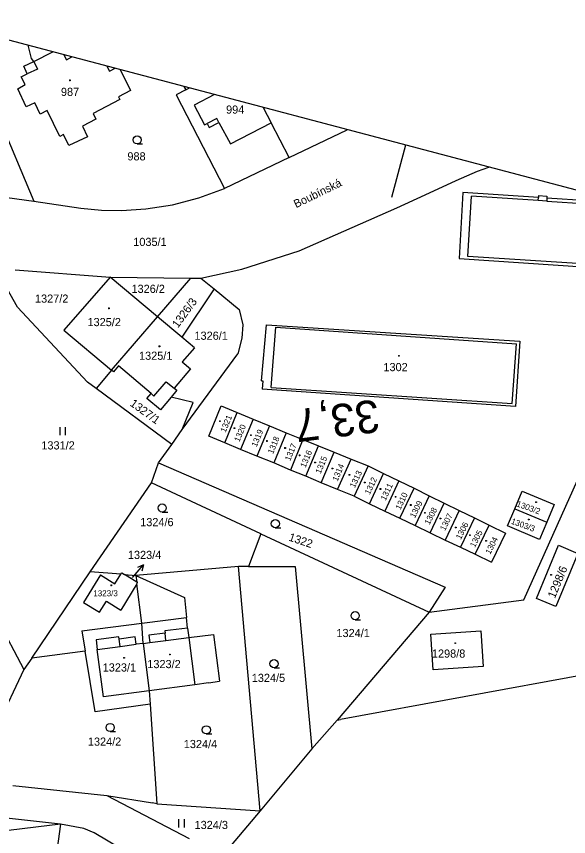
# Model space of a CAD drawing. Extents: x -805011 to -803920, y -1150790 to -1150234.
# Drawn here: x -804600.8 to -804499.4, y -1150469 to -1150318.2 of the extents above; entities that cross this region are included whole.
import ezdxf

# ---------------------------------------------------------------- set-up
doc = ezdxf.new("R2010")
doc.units = 0
for name, color, linetype in [('Default', 7, 'Continuous'), ('formát', 7, 'Continuous'), ('kilometráž - vrstava 7', 7, 'Continuous'), ('kn_celek - Cisla parcel pomocna', 7, 'Continuous'), ('kn_celek - Cisla pozemkovych parcel', 7, 'Continuous'), ('kn_celek - Cisla stavebnich parcel', 7, 'Continuous'), ('kn_celek - Dalsi prvky mapy popis', 7, 'Continuous'), ('kn_celek - Hranice parcel', 7, 'Continuous'), ('kn_celek - Vnitrni kresby', 7, 'Continuous'), ('kn_celek - Znacky budov', 7, 'Continuous'), ('kn_celek - Znacky kultur', 7, 'Continuous')]:
    doc.layers.add(name, color=color, linetype=linetype)

# ---------------------------------------------------------------- blocks, each defined once
blk = doc.blocks.new('304')
at = {"layer": 'Default'}
blk.add_line((-0.1, 0), (9.9, 0), dxfattribs=at)
blk.add_circle((-0.1, 7.5), 7.5, dxfattribs=at)
blk = doc.blocks.new('306')
at = {"layer": 'Default'}
for p, q in [((-5.2, 0), (-5.2, 15)), ((4.8, 0), (4.8, 15))]:
    blk.add_line(p, q, dxfattribs=at)
blk = doc.blocks.new('402')
at = {"layer": 'Default'}
for p, q in [((-0.8, 0.8), (0.7, 0.8)), ((-0.8, 0.8), (-0.8, -0.7)), ((0.7, 0.8), (0.7, -0.7)), ((0.7, -0.7), (-0.8, -0.7))]:
    blk.add_line(p, q, dxfattribs=at)
blk = doc.blocks.new('Z61')
at = {"layer": 'Default'}
for p, q in [((0, 0), (30, 0)), ((30, 0), (19.2, 5.3)), ((30, 0), (19.2, -5.3))]:
    blk.add_line(p, q, dxfattribs=at)

msp = doc.modelspace()

# ---------------------------------------------------------------- linework, layer by layer
at = {"layer": 'formát'}
for p, q in [((-804326.3, -1150395.58), (-804935.34, -1150234.42)), ((-804529.32, -1150341.86), (-804531.87, -1150351.53)), ((-804529.32, -1150341.86), (-804531.87, -1150351.53))]:
    msp.add_line(p, q, dxfattribs=at)
at = {"layer": 'kn_celek - Cisla parcel pomocna'}
msp.add_line((-804579.45, -1150421.34), (-804579.43, -1150421.32), dxfattribs=at)
at = {"layer": 'kn_celek - Hranice parcel'}
for p, q in [((-804610.94, -1150320.55), (-804597.6, -1150352.18)), ((-804598.01, -1150325.92), (-804598.68, -1150323.51)), ((-804597.63, -1150326.47), (-804594.11, -1150324.72)), ((-804599.42, -1150327.37), (-804597.63, -1150326.47)), ((-804597.63, -1150326.47), (-804598.01, -1150325.92)), ((-804592.08, -1150325.25), (-804591.63, -1150326.16)), ((-804591.63, -1150326.16), (-804590.6, -1150325.65)), ((-804598.84, -1150328.79), (-804599.42, -1150327.37)), ((-804584.18, -1150327.34), (-804583.71, -1150328.27)), ((-804583.71, -1150328.27), (-804582.68, -1150327.74)), ((-804581.77, -1150327.98), (-804579.86, -1150331.85)), ((-804599.96, -1150329.31), (-804598.84, -1150328.79)), ((-804599.21, -1150330.74), (-804599.96, -1150329.31)), ((-804600.53, -1150331.52), (-804599.21, -1150330.74)), ((-804599.01, -1150334.84), (-804600.53, -1150331.52)), ((-804579.86, -1150331.85), (-804582.06, -1150333)), ((-804569.69, -1150331.71), (-804571.48, -1150332.63)), ((-804570.05, -1150331.08), (-804569.69, -1150331.71)), ((-804569.69, -1150331.71), (-804569, -1150331.36)), ((-804581.8, -1150333.49), (-804586.74, -1150336.04)), ((-804582.06, -1150333), (-804581.8, -1150333.49)), ((-804571.48, -1150332.63), (-804562.59, -1150349.86)), ((-804597.45, -1150334.11), (-804599.01, -1150334.84)), ((-804596.43, -1150336.15), (-804597.45, -1150334.11)), ((-804595.18, -1150335.53), (-804596.43, -1150336.15)), ((-804592.86, -1150340.29), (-804595.18, -1150335.53)), ((-804555.45, -1150334.95), (-804553.98, -1150337.75)), ((-804586.74, -1150336.04), (-804586.19, -1150337.1)), ((-804586.19, -1150337.1), (-804588.68, -1150338.39)), ((-804588.68, -1150338.39), (-804587.78, -1150340.36)), ((-804550.72, -1150344.17), (-804553.98, -1150337.75)), ((-804592.13, -1150339.94), (-804592.86, -1150340.29)), ((-804591.19, -1150341.91), (-804592.13, -1150339.94)), ((-804550.72, -1150344.17), (-804540.02, -1150339.03)), ((-804587.78, -1150340.36), (-804591.19, -1150341.91)), ((-804550.72, -1150344.17), (-804562.59, -1150349.86)), ((-804516.1, -1150346.63), (-804513.99, -1150345.92)), ((-804520.04, -1150348.36), (-804516.1, -1150346.63)), ((-804525.7, -1150351.03), (-804520.04, -1150348.36)), ((-804567.3, -1150351.55), (-804562.59, -1150349.86)), ((-804518.79, -1150350.6), (-804519.49, -1150362.73)), ((-804504.91, -1150351.52), (-804518.79, -1150350.6)), ((-804608.15, -1150350.71), (-804597.6, -1150352.18)), ((-804572.16, -1150352.85), (-804567.3, -1150351.55)), ((-804530.92, -1150353.37), (-804525.7, -1150351.03)), ((-804504.89, -1150351.14), (-804504.91, -1150351.52)), ((-804504.89, -1150351.14), (-804503.35, -1150351.28)), ((-804503.35, -1150351.28), (-804503.36, -1150351.63)), ((-804488.71, -1150352.61), (-804503.36, -1150351.63)), ((-804597.6, -1150352.18), (-804588.95, -1150353.47)), ((-804588.95, -1150353.47), (-804585.18, -1150353.82)), ((-804581.48, -1150353.88), (-804577.03, -1150353.56)), ((-804577.03, -1150353.56), (-804572.16, -1150352.85)), ((-804548.89, -1150361.28), (-804530.92, -1150353.37)), ((-804585.18, -1150353.82), (-804581.48, -1150353.88)), ((-804559.37, -1150364.69), (-804548.89, -1150361.28)), ((-804519.49, -1150362.73), (-804473.23, -1150365.78)), ((-804601.03, -1150364.78), (-804583.56, -1150366.12)), ((-804566.93, -1150366.32), (-804559.37, -1150364.69)), ((-804583.56, -1150366.12), (-804592.09, -1150375.9)), ((-804583.56, -1150366.12), (-804568.74, -1150366.3)), ((-804574.87, -1150373.43), (-804583.56, -1150366.12)), ((-804574.87, -1150373.43), (-804568.74, -1150366.3)), ((-804568.74, -1150366.3), (-804566.93, -1150366.32)), ((-804566.93, -1150366.32), (-804564.5, -1150368.32)), ((-804600.6, -1150371.69), (-804602.54, -1150368.31)), ((-804564.5, -1150368.32), (-804570.4, -1150377.19)), ((-804564.5, -1150368.32), (-804559.89, -1150372.11)), ((-804587.74, -1150385.43), (-804600.6, -1150371.69)), ((-804559.89, -1150372.11), (-804559.19, -1150374.93)), ((-804583.33, -1150383.27), (-804574.87, -1150373.43)), ((-804570.4, -1150377.19), (-804574.87, -1150373.43)), ((-804592.09, -1150375.9), (-804583.33, -1150383.27)), ((-804559.19, -1150374.93), (-804559.41, -1150377.37)), ((-804555.76, -1150385.2), (-804554.89, -1150374.91)), ((-804554.89, -1150374.91), (-804508.29, -1150377.94)), ((-804568.11, -1150379.12), (-804570.4, -1150377.19)), ((-804559.41, -1150377.37), (-804560.15, -1150380.25)), ((-804568.11, -1150379.12), (-804570.33, -1150381.74)), ((-804508.29, -1150377.94), (-804509.12, -1150389.92)), ((-804570.35, -1150394.18), (-804560.15, -1150380.25)), ((-804570.33, -1150381.74), (-804568.85, -1150383.02)), ((-804583.33, -1150383.27), (-804586.18, -1150386.59)), ((-804582.99, -1150383.56), (-804583.33, -1150383.27)), ((-804582.03, -1150382.44), (-804582.99, -1150383.56)), ((-804576.07, -1150387.55), (-804582.03, -1150382.44)), ((-804568.85, -1150383.02), (-804571.8, -1150386.54)), ((-804555.76, -1150385.2), (-804555.52, -1150385.22)), ((-804555.52, -1150385.22), (-804555.65, -1150386.72)), ((-804586.18, -1150386.59), (-804587.74, -1150385.43)), ((-804572.26, -1150396.92), (-804586.18, -1150386.59)), ((-804571.8, -1150386.54), (-804571.33, -1150386.93)), ((-804509.12, -1150389.92), (-804555.65, -1150386.72)), ((-804576.84, -1150388.45), (-804576.07, -1150387.55)), ((-804572.4, -1150388.21), (-804574.33, -1150390.51)), ((-804571.33, -1150386.93), (-804572.4, -1150388.21)), ((-804568.32, -1150389.18), (-804572.4, -1150388.21)), ((-804574.33, -1150390.51), (-804576.84, -1150388.45)), ((-804570.35, -1150394.18), (-804568.32, -1150389.18)), ((-804565.48, -1150395.39), (-804563.21, -1150389.81)), ((-804563.21, -1150389.81), (-804560.24, -1150391.03)), ((-804562.53, -1150396.6), (-804560.24, -1150391.03)), ((-804560.24, -1150391.03), (-804557.32, -1150392.24)), ((-804557.32, -1150392.24), (-804559.61, -1150397.81)), ((-804557.32, -1150392.24), (-804554.33, -1150393.48)), ((-804572.26, -1150396.92), (-804570.35, -1150394.18)), ((-804554.33, -1150393.48), (-804556.62, -1150399.04)), ((-804554.33, -1150393.48), (-804551.25, -1150394.75)), ((-804562.53, -1150396.6), (-804565.48, -1150395.39)), ((-804551.25, -1150394.75), (-804553.54, -1150400.31)), ((-804551.25, -1150394.75), (-804548.2, -1150396)), ((-804574.73, -1150400.29), (-804572.26, -1150396.92)), ((-804559.61, -1150397.81), (-804562.53, -1150396.6)), ((-804548.2, -1150396), (-804550.43, -1150401.62)), ((-804548.2, -1150396), (-804545.32, -1150397.16)), ((-804547.66, -1150402.76), (-804545.32, -1150397.16)), ((-804545.32, -1150397.16), (-804542.4, -1150398.34)), ((-804556.62, -1150399.04), (-804559.61, -1150397.81)), ((-804544.83, -1150403.93), (-804542.4, -1150398.34)), ((-804542.4, -1150398.34), (-804539.29, -1150399.6)), ((-804576.01, -1150403.97), (-804574.73, -1150400.29)), ((-804574.73, -1150400.29), (-804522.03, -1150423.17)), ((-804553.54, -1150400.31), (-804556.62, -1150399.04)), ((-804550.43, -1150401.62), (-804553.54, -1150400.31)), ((-804541.82, -1150405.18), (-804539.29, -1150399.6)), ((-804539.29, -1150399.6), (-804536.16, -1150400.86)), ((-804507.58, -1150425.47), (-804496.15, -1150399.93)), ((-804619.21, -1150401.17), (-804599.42, -1150438.27)), ((-804547.66, -1150402.76), (-804550.43, -1150401.62)), ((-804536.16, -1150400.86), (-804538.78, -1150406.43)), ((-804536.16, -1150400.86), (-804533.35, -1150402.24)), ((-804544.83, -1150403.93), (-804547.66, -1150402.76)), ((-804535.93, -1150407.79), (-804533.35, -1150402.24)), ((-804533.35, -1150402.24), (-804530.56, -1150403.6)), ((-804587.24, -1150420.31), (-804576.01, -1150403.97)), ((-804555.88, -1150413.34), (-804576.01, -1150403.97)), ((-804541.82, -1150405.18), (-804544.83, -1150403.93)), ((-804530.56, -1150403.6), (-804533.11, -1150409.15)), ((-804530.56, -1150403.6), (-804527.76, -1150404.97)), ((-804538.78, -1150406.43), (-804541.82, -1150405.18)), ((-804538.78, -1150406.43), (-804535.93, -1150407.79)), ((-804530.34, -1150410.48), (-804527.76, -1150404.97)), ((-804527.76, -1150404.97), (-804524.99, -1150406.33)), ((-804524.99, -1150406.33), (-804527.56, -1150411.81)), ((-804524.99, -1150406.33), (-804522.22, -1150407.69)), ((-804509.23, -1150408.71), (-804507.89, -1150405.5)), ((-804507.89, -1150405.5), (-804502, -1150407.96)), ((-804535.93, -1150407.79), (-804533.11, -1150409.15)), ((-804524.79, -1150413.14), (-804522.22, -1150407.69)), ((-804522.22, -1150407.69), (-804519.45, -1150409.04)), ((-804502, -1150407.96), (-804503.35, -1150411.17)), ((-804533.11, -1150409.15), (-804530.34, -1150410.48)), ((-804519.45, -1150409.04), (-804522.01, -1150414.47)), ((-804519.45, -1150409.04), (-804516.67, -1150410.4)), ((-804510.56, -1150411.89), (-804509.23, -1150408.71)), ((-804509.23, -1150408.71), (-804503.35, -1150411.17)), ((-804530.34, -1150410.48), (-804527.56, -1150411.81)), ((-804516.67, -1150410.4), (-804519.24, -1150415.8)), ((-804516.67, -1150410.4), (-804513.94, -1150411.74)), ((-804527.56, -1150411.81), (-804524.79, -1150413.14)), ((-804516.51, -1150417.1), (-804513.94, -1150411.74)), ((-804513.94, -1150411.74), (-804510.98, -1150413.19)), ((-804504.68, -1150414.36), (-804510.56, -1150411.89)), ((-804503.35, -1150411.17), (-804504.68, -1150414.36)), ((-804555.88, -1150413.34), (-804558.18, -1150419.35)), ((-804555.88, -1150413.34), (-804524.97, -1150427.75)), ((-804524.79, -1150413.14), (-804522.01, -1150414.47)), ((-804510.98, -1150413.19), (-804513.55, -1150418.52)), ((-804522.01, -1150414.47), (-804519.24, -1150415.8)), ((-804505.26, -1150425.23), (-804501.23, -1150415.44)), ((-804501.23, -1150415.44), (-804497.65, -1150416.93)), ((-804519.24, -1150415.8), (-804516.51, -1150417.1)), ((-804497.65, -1150416.93), (-804501.68, -1150426.69)), ((-804516.51, -1150417.1), (-804513.55, -1150418.52)), ((-804559.99, -1150419.36), (-804578.84, -1150421.02)), ((-804558.18, -1150419.35), (-804559.99, -1150419.36)), ((-804556.02, -1150464.26), (-804559.99, -1150419.36)), ((-804558.18, -1150419.35), (-804549.59, -1150419.33)), ((-804549.59, -1150419.33), (-804546.53, -1150452.86)), ((-804597.99, -1150436.17), (-804587.24, -1150420.31)), ((-804585.35, -1150420.87), (-804588.48, -1150425.97)), ((-804581.64, -1150420.78), (-804587.24, -1150420.31)), ((-804585.35, -1150420.87), (-804582.7, -1150422.5)), ((-804582.7, -1150422.5), (-804581.64, -1150420.78)), ((-804581.64, -1150420.78), (-804581.47, -1150420.51)), ((-804581.47, -1150420.51), (-804580.93, -1150420.84)), ((-804578.69, -1150422.21), (-804580.93, -1150420.84)), ((-804580.93, -1150420.84), (-804578.84, -1150421.02)), ((-804578.84, -1150421.02), (-804569.95, -1150425.04)), ((-804578.84, -1150421.02), (-804578.69, -1150422.21)), ((-804578.66, -1150422.5), (-804581.63, -1150427.34)), ((-804578.69, -1150422.21), (-804578.54, -1150422.31)), ((-804578.66, -1150422.5), (-804578.54, -1150422.31)), ((-804577.78, -1150429.75), (-804578.66, -1150422.5)), ((-804522.03, -1150423.17), (-804524.97, -1150427.75)), ((-804588.48, -1150425.97), (-804585.55, -1150427.76)), ((-804585.55, -1150427.76), (-804584.28, -1150425.71)), ((-804584.28, -1150425.71), (-804581.63, -1150427.34)), ((-804569.95, -1150425.04), (-804569.57, -1150428.7)), ((-804524.97, -1150427.75), (-804507.58, -1150425.47)), ((-804501.68, -1150426.69), (-804505.26, -1150425.23)), ((-804569.37, -1150430.66), (-804569.57, -1150428.7)), ((-804524.97, -1150427.75), (-804541.85, -1150447.6)), ((-804577.54, -1150433.47), (-804577.78, -1150429.75)), ((-804569.37, -1150430.66), (-804569.15, -1150432.37)), ((-804569.15, -1150432.37), (-804564.6, -1150431.82)), ((-804564.6, -1150431.82), (-804563.5, -1150440.4)), ((-804457.42, -1150432.08), (-804541.27, -1150447.49)), ((-804524.68, -1150431.81), (-804515.47, -1150431.2)), ((-804524.27, -1150438.36), (-804524.68, -1150431.81)), ((-804515.47, -1150431.2), (-804515.04, -1150437.73)), ((-804577.54, -1150433.47), (-804576.42, -1150442.18)), ((-804588.2, -1150434.88), (-804597.99, -1150436.17)), ((-804586.37, -1150446.06), (-804588.2, -1150434.88)), ((-804597.99, -1150436.17), (-804599.42, -1150438.27)), ((-804515.04, -1150437.73), (-804524.27, -1150438.36)), ((-804599.42, -1150438.27), (-804608.69, -1150457.72)), ((-804568.02, -1150441.07), (-804576.42, -1150442.18)), ((-804565.54, -1150440.7), (-804568.02, -1150441.07)), ((-804565.54, -1150440.7), (-804563.5, -1150440.4)), ((-804576.42, -1150442.18), (-804576.26, -1150444.67)), ((-804576.26, -1150444.67), (-804586.37, -1150446.06)), ((-804576.26, -1150444.67), (-804575.03, -1150462.95)), ((-804541.85, -1150447.6), (-804546.53, -1150452.86)), ((-804541.85, -1150447.6), (-804541.27, -1150447.49)), ((-804546.53, -1150452.86), (-804556.02, -1150464.26)), ((-804601.47, -1150459.58), (-804584.21, -1150461.47)), ((-804584.21, -1150461.47), (-804575.81, -1150462.79)), ((-804584.21, -1150461.47), (-804569.06, -1150469.36)), ((-804575.03, -1150462.95), (-804575.81, -1150462.79)), ((-804575.03, -1150462.95), (-804556.02, -1150464.26)), ((-804592.74, -1150466.72), (-804607.47, -1150465.11)), ((-804556.02, -1150464.26), (-804563.32, -1150472.84)), ((-804592.74, -1150466.72), (-804605.13, -1150468.22)), ((-804592.74, -1150466.72), (-804596.82, -1150498.15)), ((-804588.4, -1150467.53), (-804592.74, -1150466.72)), ((-804586.55, -1150468.28), (-804588.4, -1150467.53)), ((-804578.81, -1150472.86), (-804586.55, -1150468.28))]:
    msp.add_line(p, q, dxfattribs=at)
at = {"layer": 'kn_celek - Vnitrni kresby'}
for p, q in [((-804597.63, -1150326.47), (-804596.93, -1150327.89)), ((-804596.93, -1150327.89), (-804598.84, -1150328.79)), ((-804564.39, -1150332.58), (-804568.15, -1150334.55)), ((-804568.15, -1150334.55), (-804566.23, -1150338.16)), ((-804564.01, -1150336.99), (-804565.78, -1150337.92)), ((-804563.63, -1150337.7), (-804564.01, -1150336.99)), ((-804566.23, -1150338.16), (-804565.78, -1150337.92)), ((-804565.78, -1150337.92), (-804565.41, -1150338.64)), ((-804565.41, -1150338.64), (-804563.63, -1150337.7)), ((-804563.63, -1150337.7), (-804561.5, -1150341.61)), ((-804561.5, -1150341.61), (-804553.98, -1150337.75)), ((-804517.87, -1150362.32), (-804517.18, -1150351.24)), ((-804504.94, -1150352.05), (-804517.18, -1150351.24)), ((-804504.94, -1150352.05), (-804504.91, -1150351.52)), ((-804503.37, -1150352.16), (-804504.94, -1150352.05)), ((-804503.36, -1150351.63), (-804503.37, -1150352.16)), ((-804503.37, -1150352.16), (-804486.73, -1150353.26)), ((-804473.7, -1150365.24), (-804517.87, -1150362.32)), ((-804554, -1150386.43), (-804553.16, -1150375.33)), ((-804553.16, -1150375.33), (-804508.95, -1150378.38)), ((-804509.72, -1150389.37), (-804508.95, -1150378.38)), ((-804575.54, -1150388.01), (-804573.29, -1150385.38)), ((-804573.29, -1150385.38), (-804571.8, -1150386.54)), ((-804554, -1150386.43), (-804509.72, -1150389.37)), ((-804576.07, -1150387.55), (-804575.54, -1150388.01)), ((-804577.78, -1150429.75), (-804569.57, -1150428.7)), ((-804588.81, -1150431.15), (-804577.78, -1150429.75)), ((-804588.81, -1150431.15), (-804588.2, -1150434.88)), ((-804573.5, -1150431.58), (-804576.47, -1150431.97)), ((-804576.47, -1150431.97), (-804576.3, -1150433.31)), ((-804569.37, -1150430.66), (-804573.56, -1150431.18)), ((-804573.56, -1150431.18), (-804573.5, -1150431.58)), ((-804573.33, -1150432.92), (-804573.5, -1150431.58)), ((-804581.98, -1150432.29), (-804586.18, -1150432.84)), ((-804586.18, -1150432.84), (-804585.95, -1150434.58)), ((-804581.93, -1150432.68), (-804581.98, -1150432.29)), ((-804578.97, -1150432.3), (-804581.93, -1150432.68)), ((-804581.75, -1150434.03), (-804581.93, -1150432.68)), ((-804578.79, -1150433.64), (-804578.97, -1150432.3)), ((-804577.54, -1150433.47), (-804578.79, -1150433.64)), ((-804577.54, -1150433.47), (-804576.3, -1150433.31)), ((-804576.3, -1150433.31), (-804573.33, -1150432.92)), ((-804573.33, -1150432.92), (-804569.15, -1150432.37)), ((-804569.15, -1150432.37), (-804568.02, -1150441.07)), ((-804585.95, -1150434.58), (-804581.75, -1150434.03)), ((-804584.83, -1150443.3), (-804585.95, -1150434.58)), ((-804581.75, -1150434.03), (-804578.79, -1150433.64)), ((-804576.42, -1150442.18), (-804584.83, -1150443.3))]:
    msp.add_line(p, q, dxfattribs=at)

# ---------------------------------------------------------------- block references
at = {"layer": 'kn_celek - Cisla parcel pomocna', "xscale": 0.1, "yscale": 0.10000000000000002, "rotation": 49.73940000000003}
msp.add_blockref('Z61', (-804579.43, -1150421.32), dxfattribs=at)
at = {"layer": 'kn_celek - Znacky budov', "xscale": 0.1, "yscale": 0.10000000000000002}
for p in [(-804590.98, -1150329.97), (-804583.84, -1150371.89), (-804574.55, -1150378.88), (-804530.55, -1150380.6), (-804563.43, -1150392.61), (-804560.76, -1150393.9), (-804557.75, -1150395.2), (-804554.78, -1150396.27), (-804551.45, -1150397.57), (-804548.79, -1150398.92), (-804545.95, -1150400.22), (-804542.75, -1150401.32), (-804539.64, -1150402.51), (-804536.82, -1150403.9), (-804533.95, -1150405.11), (-804531.15, -1150406.54), (-804505.35, -1150407.52), (-804528.36, -1150408.05), (-804525.75, -1150409.49), (-804522.91, -1150410.51), (-804506.69, -1150410.71), (-804520.11, -1150412.16), (-804517.51, -1150413.6), (-804514.53, -1150414.63), (-804502.59, -1150420.88), (-804583.41, -1150422.8), (-804520.2, -1150433.44), (-804581.03, -1150436.15), (-804572.63, -1150435.52)]:
    msp.add_blockref('402', p, dxfattribs=at)
at = {"layer": 'kn_celek - Znacky kultur', "xscale": 0.1, "yscale": 0.10000000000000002}
for name, p in [('304', (-804578.62, -1150341.66)), ('306', (-804592.27, -1150395.22)), ('304', (-804574.01, -1150409.33)), ('304', (-804553.23, -1150412.22)), ('304', (-804538.57, -1150429.14)), ('304', (-804553.47, -1150437.97)), ('304', (-804583.58, -1150449.69)), ('304', (-804565.92, -1150450.13)), ('306', (-804570.43, -1150467.3))]:
    msp.add_blockref(name, p, dxfattribs=at)

# ---------------------------------------------------------------- texts
at = {"layer": 'kilometráž - vrstava 7'}
msp.add_text('33,7', height=6, rotation=187.2569, dxfattribs=at).set_placement((-804534.52, -1150388.59))
at = {"layer": 'kn_celek - Cisla parcel pomocna'}
msp.add_text('1323/4', height=1.5, dxfattribs=at).set_placement((-804580.33, -1150417.96))
at = {"layer": 'kn_celek - Cisla pozemkovych parcel'}
for s, height, p in [('988', 1.5, (-804580.42, -1150344.68)), ('1035/1', 1.5, (-804579.34, -1150360.41)), ('1326/2', 1.5, (-804579.67, -1150369.04)), ('1327/2', 1.5, (-804597.4, -1150370.84)), ('1326/1', 1.5, (-804568.1, -1150377.66)), ('1331/2', 1.5, (-804596.23, -1150397.82)), ('1324/6', 1.5, (-804578.07, -1150411.93)), ('1323/4', 0.1, (-804579.72, -1150421.31)), ('1324/1', 1.5, (-804542.01, -1150432.32)), ('1324/5', 1.5, (-804557.57, -1150440.57)), ('1324/2', 1.5, (-804587.68, -1150452.29)), ('1324/4', 1.5, (-804570.06, -1150452.73)), ('1324/3', 1.5, (-804568.08, -1150467.61))]:
    msp.add_text(s, height=height, dxfattribs=at).set_placement(p)
for s, rotation, p in [('1326/3', 54, (-804571.14, -1150375.61)), ('1327/1', 324, (-804580.08, -1150389.66)), ('1322', 341.5151, (-804550.91, -1150414.55))]:
    msp.add_text(s, height=1.5, rotation=rotation, dxfattribs=at).set_placement(p)
at = {"layer": 'kn_celek - Cisla stavebnich parcel'}
for s, height, p in [('987', 1.5, (-804592.63, -1150332.83)), ('994', 1.5, (-804562.29, -1150336.08)), ('1325/2', 1.5, (-804587.75, -1150375.15)), ('1325/1', 1.5, (-804578.28, -1150381.34)), ('1302', 1.5, (-804533.38, -1150383.43)), ('1323/3', 1.1, (-804586.68, -1150424.81)), ('1298/8', 1.5, (-804524.47, -1150436.1)), ('1323/2', 1.5, (-804576.76, -1150438.03)), ('1323/1', 1.5, (-804584.96, -1150438.65))]:
    msp.add_text(s, height=height, dxfattribs=at).set_placement(p)
for s, height, rotation, p in [('1321', 1.1, 67.5, (-804562.39, -1150394.8)), ('1320', 1.1, 67.5, (-804559.85, -1150396.53)), ('1319', 1.1, 67.5, (-804556.68, -1150397.46)), ('1318', 1.1, 67.5, (-804553.68, -1150398.75)), ('1317', 1.1, 67.5, (-804550.52, -1150400.03)), ('1316', 1.1, 67.5, (-804547.7, -1150401.27)), ('1315', 1.1, 67.5, (-804544.92, -1150402.38)), ('1314', 1.1, 67.5, (-804541.8, -1150403.77)), ('1313', 1.1, 64.8, (-804538.65, -1150404.99)), ('1312', 1.1, 64.8, (-804535.9, -1150406.22)), ('1311', 1.1, 64.8, (-804532.98, -1150407.32)), ('1310', 1.1, 64.8, (-804530.26, -1150409.02)), ('1309', 1.1, 63, (-804527.61, -1150410.52)), ('1303/2', 1.1, 340.2, (-804509.02, -1150408.26)), ('1308', 1.1, 63, (-804524.93, -1150411.77)), ('1307', 1.1, 63, (-804522.08, -1150412.87)), ('1303/3', 1.1, 340.2, (-804510.03, -1150411.45)), ('1306', 1.1, 63, (-804519.17, -1150414.47)), ('1305', 1.1, 63, (-804516.58, -1150415.93)), ('1304', 1.1, 63, (-804513.76, -1150417.19)), ('1298/6', 1.5, 67.5, (-804501.88, -1150425.31))]:
    msp.add_text(s, height=height, rotation=rotation, dxfattribs=at).set_placement(p)
at = {"layer": 'kn_celek - Dalsi prvky mapy popis'}
msp.add_text('Boubínská', height=1.5, rotation=25.9496, dxfattribs=at).set_placement((-804549.42, -1150353.47))

doc.saveas('drawing.dxf')
